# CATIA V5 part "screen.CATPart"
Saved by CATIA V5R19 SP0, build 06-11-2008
Part number: screen
Bounding box of the stored display mesh (mm): x -45.72 to -7.62, y -27.084 to 27.084, z -2.54 to 0.254
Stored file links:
  F:\CAD\ipod\screen.CATPart
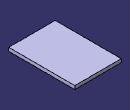
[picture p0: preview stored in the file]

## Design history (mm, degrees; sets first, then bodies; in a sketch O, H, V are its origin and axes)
Body1 (main body)
  DatumSurface1
  DatumCurve1 to DatumCurve4
  Sketch1 on face of DatumSurface1, origin (0, 0, -2.54), H (1, 0, 0), V (0, 1, 0)
    line L1 (-45.72, 27.0839) -> (-7.62, 27.0839)
    line L2 (-7.62, 27.0839) -> (-7.62, -27.0839)
    line L3 (-7.62, -27.0839) -> (-45.72, -27.0839)
    line L4 (-45.72, -27.0839) -> (-45.72, 27.0839)
    reference projected line E1 (-7.62, 27.0839) -> (-45.72, 27.0839) from edge of DatumCurve1
    reference projected line E2 (-45.72, -27.0839) -> (-7.62, -27.0839) from edge of DatumCurve2
    reference projected line E3 (-45.72, 27.0839) -> (-45.72, -27.0839) from edge of DatumCurve3
    reference projected line E4 (-7.62, -27.0839) -> (-7.62, 27.0839) from edge of DatumCurve4
    horizontal: L1 H, L3 H
    vertical: L2 V, L4 V
    coincidence: L1 E1, L3 E2, L4 E3, L2 E4
  Pad1: profile Sketch1, direction (0, 0, 1), length 2.794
